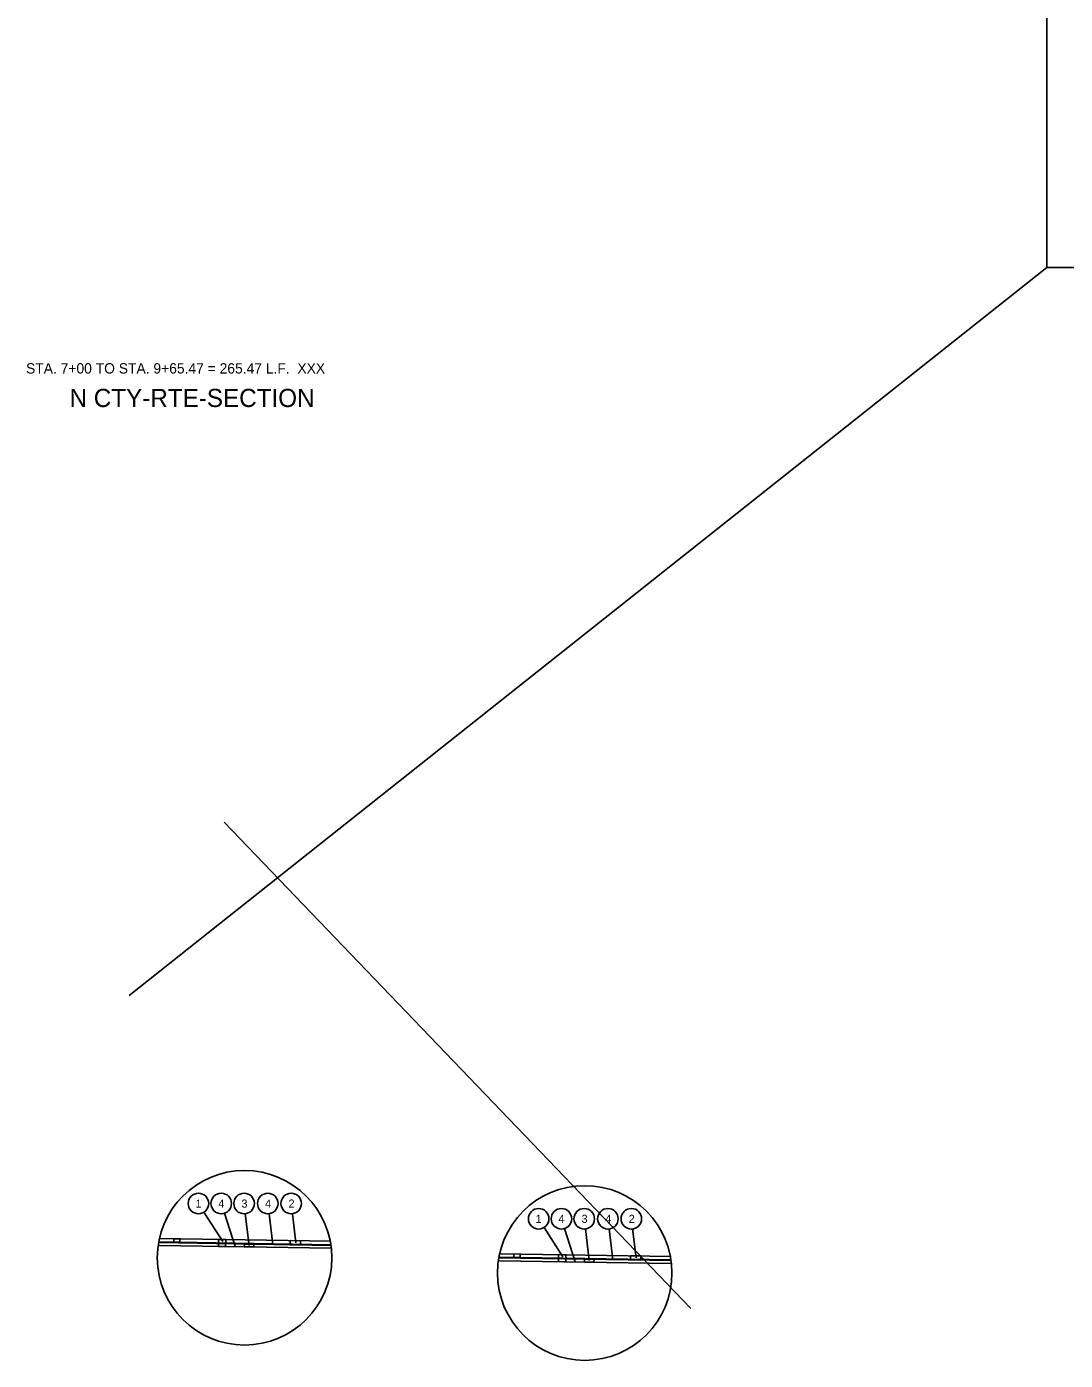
# Model space of a CAD drawing. Extents: x -196 to 300, y -73 to 205.
# Drawn here: x -68.6 to 1.2, y -73.5 to 16.2 of the extents above; entities that cross this region are included whole.
import ezdxf

# ---------------------------------------------------------------- set-up
doc = ezdxf.new("R2010")
doc.units = 0
for name, color, linetype in [('Level 1', 7, 'Continuous'), ('Level 4', 7, 'Continuous'), ('SC_Scratch1', 7, 'Continuous'), ('SH_Cut_Line', 7, 'Continuous')]:
    doc.layers.add(name, color=color, linetype=linetype)

msp = doc.modelspace()

# ---------------------------------------------------------------- linework, layer by layer
at = {"layer": 'Level 1'}
for p, q in [((-55.322, -37.283), (-55.322, -37.283)), ((-56.686, -63.495), (-55.424, -65.465)), ((-55.315, -63.572), (-54.6, -65.813)), ((-53.907, -63.599), (-53.649, -65.726)), ((-52.313, -63.599), (-52.063, -65.665)), ((-50.736, -63.599), (-50.5, -65.55)), ((-33.805, -64.52), (-32.543, -66.489)), ((-59.681, -65.262), (-48.152, -65.445)), ((-32.434, -64.596), (-31.72, -66.837)), ((-31.026, -64.624), (-30.768, -66.75)), ((-29.433, -64.624), (-29.182, -66.689)), ((-27.856, -64.624), (-27.619, -66.575)), ((-59.729, -65.496), (-48.156, -65.68)), ((-59.688, -65.732), (-48.159, -65.915)), ((-59.685, -65.544), (-48.156, -65.727)), ((-36.8, -66.286), (-25.272, -66.469)), ((-36.848, -66.52), (-25.275, -66.704)), ((-36.808, -66.756), (-25.279, -66.94)), ((-36.805, -66.568), (-25.276, -66.752))]:
    msp.add_line(p, q, dxfattribs=at)
for points in [[(-58.723, -65.277), (-58.304, -65.284), (-58.304, -65.519), (-58.723, -65.512)], [(-55.71, -65.325), (-55.222, -65.333), (-55.23, -65.803), (-55.718, -65.795)], [(-50.887, -65.684), (-50.192, -65.695), (-50.187, -65.413), (-50.882, -65.402)], [(-53.974, -65.823), (-53.336, -65.833), (-53.333, -65.645), (-53.971, -65.635)], [(-35.843, -66.302), (-35.423, -66.308), (-35.423, -66.543), (-35.843, -66.536)], [(-32.83, -66.349), (-32.342, -66.357), (-32.349, -66.827), (-32.837, -66.819)], [(-31.093, -66.847), (-30.455, -66.857), (-30.452, -66.669), (-31.09, -66.659)], [(-28.006, -66.708), (-27.311, -66.719), (-27.307, -66.437), (-28.002, -66.426)]]:
    msp.add_lwpolyline(points, close=True, dxfattribs=at)
for centre, radius in [((-53.958, -66.561), 5.869), ((-31.077, -67.586), 5.869), ((-57.059, -62.913), 0.691), ((-55.524, -62.913), 0.691), ((-53.99, -62.913), 0.691), ((-52.397, -62.913), 0.691), ((-50.82, -62.913), 0.691), ((-34.178, -63.938), 0.691), ((-32.644, -63.938), 0.691), ((-31.11, -63.938), 0.691), ((-29.516, -63.938), 0.691), ((-27.939, -63.938), 0.691)]:
    msp.add_circle(centre, radius, dxfattribs=at)
at = {"layer": 'SC_Scratch1'}
for p, q in [((0, 0), (-61.726, -48.926)), ((-23.938, -69.964), (-55.322, -37.283))]:
    msp.add_line(p, q, dxfattribs=at)
at = {"layer": 'SH_Cut_Line'}
msp.add_lwpolyline([(0, 0), (170, 0), (170, 110), (0, 110)], close=True, dxfattribs=at)

# ---------------------------------------------------------------- texts
at = {"layer": 'Level 1'}
for s, p in [('1', (-57.26, -63.191)), ('4', (-55.725, -63.191)), ('3', (-54.171, -63.191)), ('4', (-52.578, -63.191)), ('2', (-51.001, -63.191)), ('1', (-34.379, -64.215)), ('4', (-32.845, -64.215)), ('3', (-31.291, -64.215)), ('4', (-29.697, -64.215)), ('2', (-28.12, -64.215))]:
    msp.add_text(s, height=0.547, dxfattribs=at).set_placement(p)
at = {"layer": 'Level 4'}
for s, height, p in [('STA. 7+00 TO STA. 9+65.47 = 265.47 L.F.  XXX', 0.69658, (-68.656, -7.12)), ('N CTY-RTE-SECTION', 1.21902, (-65.73, -9.369))]:
    msp.add_text(s, height=height, dxfattribs=at).set_placement(p)

doc.saveas('drawing.dxf')
